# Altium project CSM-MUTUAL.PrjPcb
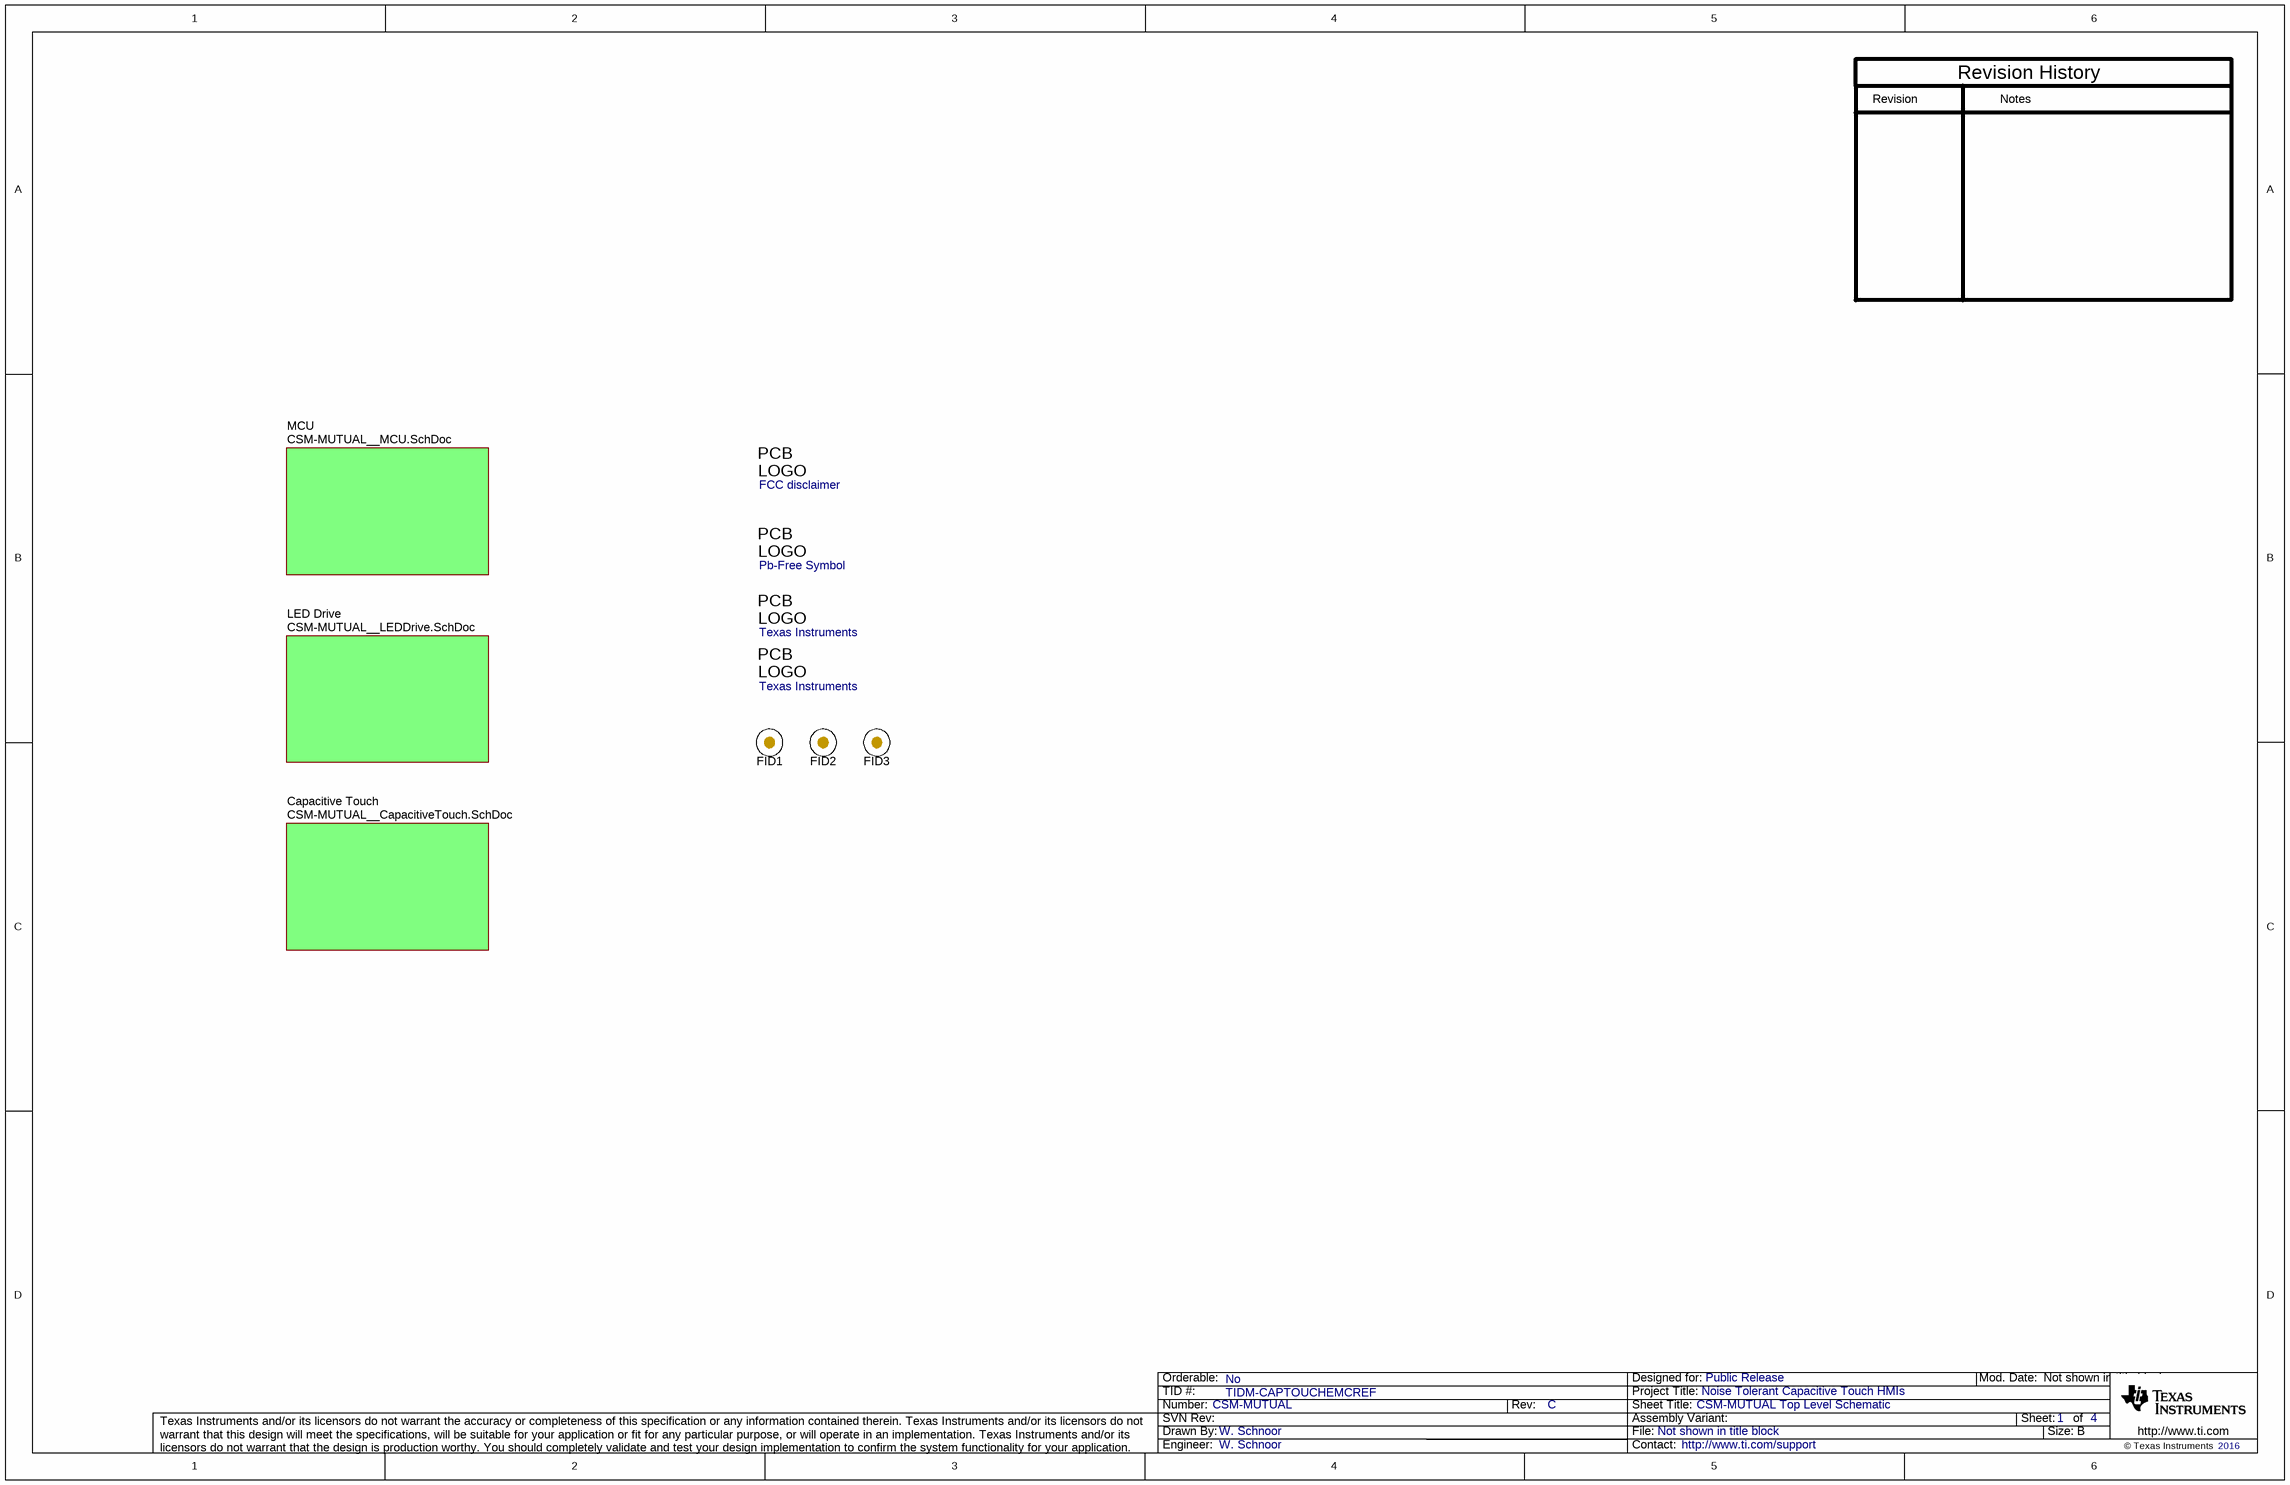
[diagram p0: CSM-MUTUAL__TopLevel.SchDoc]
TID: TIDM-CAPTOUCHEMCREF; TechSupport: http://www.ti.com/support; SCH_Rev: C; PRJ_Title: Noise Tolerant Capacitive Touch HMIs; PRJ_Number: CSM-MUTUAL; PRJ_Engineer: W. Schnoor; PRJ_Customer: Public Release; PCB_Rev: C; PCB_Layout: W. Schnoor; EVM_Orderable: No; CopyrightYear: 2016
4 sheets, 159 parts. Net scope: global (net labels, ports and power ports of the same name join across sheets).
Board file: CSM-MUTUAL.PcbDoc
Sheets:
  CSM-MUTUAL__TopLevel.SchDoc
    Capacitive Touch = CSM-MUTUAL__CapacitiveTouch.SchDoc
    LED Drive = CSM-MUTUAL__LEDDrive.SchDoc
    MCU = CSM-MUTUAL__MCU.SchDoc

## Sheet CSM-MUTUAL__TopLevel.SchDoc: CSM-MUTUAL Top Level Schematic
size 431 x 279 mm; Date: Not shown in title block; ApprovedBy: Not shown in title block; CheckedBy: Not shown in title block; Author: Not shown in title block; CompanyName: Not shown in title block; DrawnBy: W. Schnoor; Engineer: Not shown in title block; Organization: Not shown in title block; Address1: Not shown in title block; Address2: Not shown in title block; Address3: Not shown in title block; Address4: Not shown in title block; DocumentNumber: 1; Revision: Use project parameter SCH_Rev; SheetNumber: 1; SheetTotal: 4; PageSetup: Record=PageOptions¦CenterHorizontal=True¦CenterVertical=True¦PrintScale=1.00¦XCorrection=1.00¦YCorrection=1.00¦PrintKind=0¦BorderSize=5000000¦LeftOffset=0¦BottomOffset=0¦Orientation=2¦PaperLength=1000¦PaperWidth=1000¦Scale=100¦PaperSource=15¦PrintQuality=600¦MediaType=1¦DitherType=10¦PaperKind=Letter¦PrintScaleMode=1

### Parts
FCCLogo  FCC disclaimer  [FCC_disclaimer]  (no BOM)
FID1  Fiducial  [Fiducial10-30]  (value not drawn)
FID2  Fiducial  [Fiducial10-30]  (value not drawn)
FID3  Fiducial  [Fiducial10-30]  (value not drawn)
PbFreeLogo  Pb-Free Symbol  [Pb-Free_Overlay_Medium]  (no BOM)
TILogo  Texas Instruments  [TI_Stacked_Overlay_Medium]  (no BOM)
TILogoBack  Texas Instruments  [TI_Stacked_Overlay_Medium]  (no BOM)

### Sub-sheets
Capacitive Touch = CSM-MUTUAL__CapacitiveTouch.SchDoc: no entries
LED Drive = CSM-MUTUAL__LEDDrive.SchDoc: no entries
MCU = CSM-MUTUAL__MCU.SchDoc: no entries

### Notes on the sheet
- Revision
- Notes
- Revision History

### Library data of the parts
FCCLogo = FCC_disclaimer: SymbolCreator: codlsc
FID1-FID3 = Fiducial: Fiducial mark.  There is nothing to buy or mount.; SymbolCreator: codlsc
PbFreeLogo = Pb-Free: SymbolCreator: a0412235
TILogo TILogoBack = TI_Logo: Texas Instrument Corporate Signature; SymbolCreator: a0412235

## Sheet CSM-MUTUAL__CapacitiveTouch.SchDoc: CSM-MUTUAL Capacitive Touch Schematic
size 431 x 279 mm; Date: Not shown in title block; ApprovedBy: Not shown in title block; CheckedBy: Not shown in title block; Author: Not shown in title block; CompanyName: Not shown in title block; DrawnBy: W. Schnoor; Engineer: Not shown in title block; Organization: Not shown in title block; Address1: Not shown in title block; Address2: Not shown in title block; Address3: Not shown in title block; Address4: Not shown in title block; DocumentNumber: 1; Revision: Use project parameter SCH_Rev; SheetNumber: 3; SheetTotal: 4; PageSetup: Record=PageOptions¦CenterHorizontal=True¦CenterVertical=True¦PrintScale=1.00¦XCorrection=1.00¦YCorrection=1.00¦PrintKind=0¦BorderSize=5000000¦LeftOffset=0¦BottomOffset=0¦Orientation=2¦PaperLength=1000¦PaperWidth=1000¦Scale=100¦PaperSource=15¦PrintQuality=600¦MediaType=1¦DitherType=10¦PaperKind=Letter¦PrintScaleMode=1
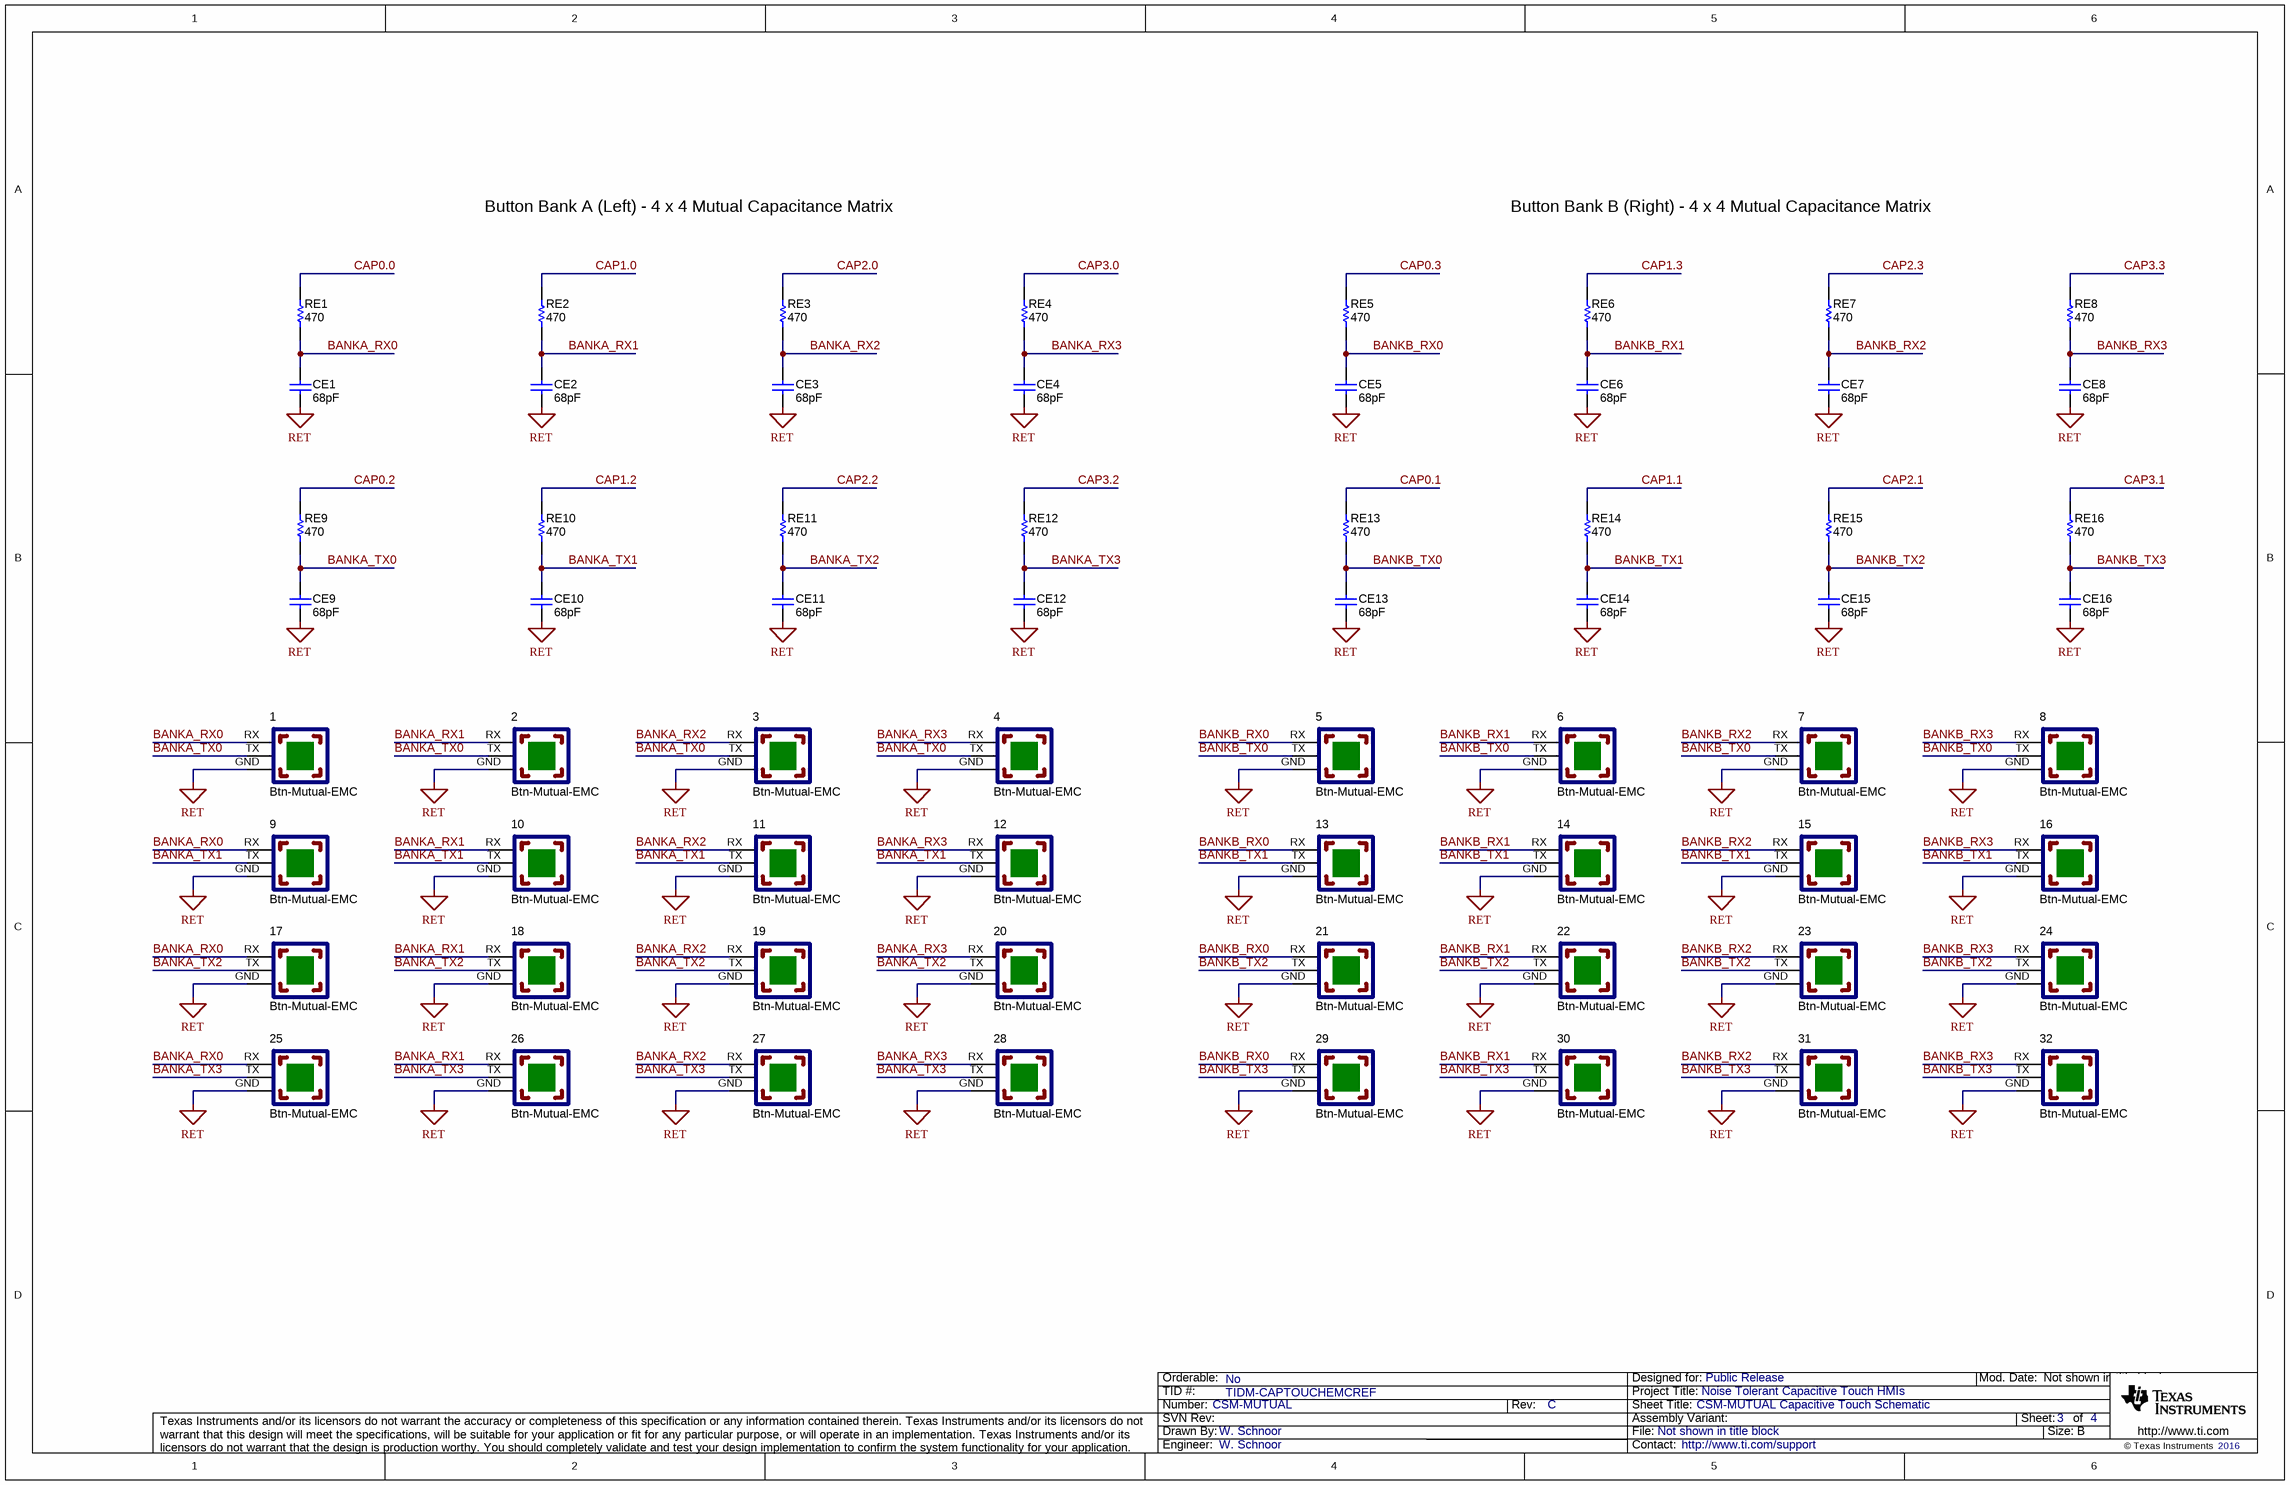
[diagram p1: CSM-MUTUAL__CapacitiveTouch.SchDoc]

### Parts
1  Btn-Mutual-EMC  [btn-mutual-emc-l-rotated]  (no BOM)
2  Btn-Mutual-EMC  [btn-mutual-emc-l-rotated]  (no BOM)
3  Btn-Mutual-EMC  [btn-mutual-emc-l-rotated]  (no BOM)
4  Btn-Mutual-EMC  [btn-mutual-emc-l-rotated]  (no BOM)
5  Btn-Mutual-EMC  [btn-mutual-emc-l-rotated]  (no BOM)
6  Btn-Mutual-EMC  [btn-mutual-emc-l-rotated]  (no BOM)
7  Btn-Mutual-EMC  [btn-mutual-emc-l-rotated]  (no BOM)
8  Btn-Mutual-EMC  [btn-mutual-emc-l-rotated]  (no BOM)
9  Btn-Mutual-EMC  [btn-mutual-emc-l-rotated]  (no BOM)
10  Btn-Mutual-EMC  [btn-mutual-emc-l-rotated]  (no BOM)
11  Btn-Mutual-EMC  [btn-mutual-emc-l-rotated]  (no BOM)
12  Btn-Mutual-EMC  [btn-mutual-emc-l-rotated]  (no BOM)
13  Btn-Mutual-EMC  [btn-mutual-emc-l-rotated]  (no BOM)
14  Btn-Mutual-EMC  [btn-mutual-emc-l-rotated]  (no BOM)
15  Btn-Mutual-EMC  [btn-mutual-emc-l-rotated]  (no BOM)
16  Btn-Mutual-EMC  [btn-mutual-emc-l-rotated]  (no BOM)
17  Btn-Mutual-EMC  [btn-mutual-emc-l-rotated]  (no BOM)
18  Btn-Mutual-EMC  [btn-mutual-emc-l-rotated]  (no BOM)
19  Btn-Mutual-EMC  [btn-mutual-emc-l-rotated]  (no BOM)
20  Btn-Mutual-EMC  [btn-mutual-emc-l-rotated]  (no BOM)
21  Btn-Mutual-EMC  [btn-mutual-emc-l-rotated]  (no BOM)
22  Btn-Mutual-EMC  [btn-mutual-emc-l-rotated]  (no BOM)
23  Btn-Mutual-EMC  [btn-mutual-emc-l-rotated]  (no BOM)
24  Btn-Mutual-EMC  [btn-mutual-emc-l-rotated]  (no BOM)
25  Btn-Mutual-EMC  [btn-mutual-emc-l-rotated]  (no BOM)
26  Btn-Mutual-EMC  [btn-mutual-emc-l-rotated]  (no BOM)
27  Btn-Mutual-EMC  [btn-mutual-emc-l-rotated]  (no BOM)
28  Btn-Mutual-EMC  [btn-mutual-emc-l-rotated]  (no BOM)
29  Btn-Mutual-EMC  [btn-mutual-emc-l-rotated]  (no BOM)
30  Btn-Mutual-EMC  [btn-mutual-emc-l-rotated]  (no BOM)
31  Btn-Mutual-EMC  [btn-mutual-emc-l-rotated]  (no BOM)
32  Btn-Mutual-EMC  [btn-mutual-emc-l-rotated]  (no BOM)
CE1  ValueDisplayed: 68pF  [0402]  (hidden comment: GRM1555C1H680JA01D)
CE2  ValueDisplayed: 68pF  [0402]  (hidden comment: GRM1555C1H680JA01D)
CE3  ValueDisplayed: 68pF  [0402]  (hidden comment: GRM1555C1H680JA01D)
CE4  ValueDisplayed: 68pF  [0402]  (hidden comment: GRM1555C1H680JA01D)
CE5  ValueDisplayed: 68pF  [0402]  (hidden comment: GRM1555C1H680JA01D)
CE6  ValueDisplayed: 68pF  [0402]  (hidden comment: GRM1555C1H680JA01D)
CE7  ValueDisplayed: 68pF  [0402]  (hidden comment: GRM1555C1H680JA01D)
CE8  ValueDisplayed: 68pF  [0402]  (hidden comment: GRM1555C1H680JA01D)
CE9  ValueDisplayed: 68pF  [0402]  (hidden comment: GRM1555C1H680JA01D)
CE10  ValueDisplayed: 68pF  [0402]  (hidden comment: GRM1555C1H680JA01D)
CE11  ValueDisplayed: 68pF  [0402]  (hidden comment: GRM1555C1H680JA01D)
CE12  ValueDisplayed: 68pF  [0402]  (hidden comment: GRM1555C1H680JA01D)
CE13  ValueDisplayed: 68pF  [0402]  (hidden comment: GRM1555C1H680JA01D)
CE14  ValueDisplayed: 68pF  [0402]  (hidden comment: GRM1555C1H680JA01D)
CE15  ValueDisplayed: 68pF  [0402]  (hidden comment: GRM1555C1H680JA01D)
CE16  ValueDisplayed: 68pF  [0402]  (hidden comment: GRM1555C1H680JA01D)
RE1  ValueDisplayed: 470  [0402]  (hidden comment: CRCW0402470RJNED)
RE2  ValueDisplayed: 470  [0402]  (hidden comment: CRCW0402470RJNED)
RE3  ValueDisplayed: 470  [0402]  (hidden comment: CRCW0402470RJNED)
RE4  ValueDisplayed: 470  [0402]  (hidden comment: CRCW0402470RJNED)
RE5  ValueDisplayed: 470  [0402]  (hidden comment: CRCW0402470RJNED)
RE6  ValueDisplayed: 470  [0402]  (hidden comment: CRCW0402470RJNED)
RE7  ValueDisplayed: 470  [0402]  (hidden comment: CRCW0402470RJNED)
RE8  ValueDisplayed: 470  [0402]  (hidden comment: CRCW0402470RJNED)
RE9  ValueDisplayed: 470  [0402]  (hidden comment: CRCW0402470RJNED)
RE10  ValueDisplayed: 470  [0402]  (hidden comment: CRCW0402470RJNED)
RE11  ValueDisplayed: 470  [0402]  (hidden comment: CRCW0402470RJNED)
RE12  ValueDisplayed: 470  [0402]  (hidden comment: CRCW0402470RJNED)
RE13  ValueDisplayed: 470  [0402]  (hidden comment: CRCW0402470RJNED)
RE14  ValueDisplayed: 470  [0402]  (hidden comment: CRCW0402470RJNED)
RE15  ValueDisplayed: 470  [0402]  (hidden comment: CRCW0402470RJNED)
RE16  ValueDisplayed: 470  [0402]  (hidden comment: CRCW0402470RJNED)

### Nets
RET: 1.GND 2.GND 3.GND 4.GND 5.GND 6.GND 7.GND 8.GND 9.GND 10.GND 11.GND 12.GND 13.GND 14.GND 15.GND 16.GND 17.GND 18.GND 19.GND 20.GND 21.GND 22.GND 23.GND 24.GND 25.GND 26.GND 27.GND 28.GND 29.GND 30.GND 31.GND 32.GND CE1.2 CE2.2 CE3.2 CE4.2 CE5.2 CE6.2 CE7.2 CE8.2 CE9.2 CE10.2 CE11.2 CE12.2 CE13.2 CE14.2 CE15.2 CE16.2
BANKA_RX0: 1.RX 9.RX 17.RX 25.RX CE1.1 RE1.1
BANKA_RX1: 2.RX 10.RX 18.RX 26.RX CE2.1 RE2.1
BANKA_RX2: 3.RX 11.RX 19.RX 27.RX CE3.1 RE3.1
BANKA_RX3: 4.RX 12.RX 20.RX 28.RX CE4.1 RE4.1
BANKA_TX0: 1.TX 2.TX 3.TX 4.TX CE9.1 RE9.1
BANKA_TX1: 9.TX 10.TX 11.TX 12.TX CE10.1 RE10.1
BANKA_TX2: 17.TX 18.TX 19.TX 20.TX CE11.1 RE11.1
BANKA_TX3: 25.TX 26.TX 27.TX 28.TX CE12.1 RE12.1
BANKB_RX0: 5.RX 13.RX 21.RX 29.RX CE5.1 RE5.1
BANKB_RX1: 6.RX 14.RX 22.RX 30.RX CE6.1 RE6.1
BANKB_RX2: 7.RX 15.RX 23.RX 31.RX CE7.1 RE7.1
BANKB_RX3: 8.RX 16.RX 24.RX 32.RX CE8.1 RE8.1
BANKB_TX0: 5.TX 6.TX 7.TX 8.TX CE13.1 RE13.1
BANKB_TX1: 13.TX 14.TX 15.TX 16.TX CE14.1 RE14.1
BANKB_TX2: 21.TX 22.TX 23.TX 24.TX CE15.1 RE15.1
BANKB_TX3: 29.TX 30.TX 31.TX 32.TX CE16.1 RE16.1
CAP0.0: RE1.2
CAP0.1: RE13.2
CAP0.2: RE9.2
CAP0.3: RE5.2
CAP1.0: RE2.2
CAP1.1: RE14.2
CAP1.2: RE10.2
CAP1.3: RE6.2
CAP2.0: RE3.2
CAP2.1: RE15.2
CAP2.2: RE11.2
CAP2.3: RE7.2
CAP3.0: RE4.2
CAP3.1: RE16.2
CAP3.2: RE12.2
CAP3.3: RE8.2

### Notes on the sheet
- Button Bank A (Left) - 4 x 4 Mutual Capacitance Matrix
- Button Bank B (Right) - 4 x 4 Mutual Capacitance Matrix

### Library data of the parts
1-32 = btn-mutual-emc: Capacitive Button, Mutual, 2-layer, EMC; Manufacturer: None; SymbolCreator: a0273983; CompType: Electrode; U/M: EA, IN, or GM
CE1-CE16 = GRM1555C1H680JA01D: CAP, CERM, 68 pF, 50 V, +/- 5%, C0G/NP0, 0402; Manufacturer: MuRata; Polarized: N; CompType: Capacitor; Value: 68pF; U/M: EA; Cap_F: 0.000000000068; Tolerance_%: 5; Value1: Unknown; VDC_V: 50; Value2: 50V; TaMin_C: -55; TaMax_C: 125; AEC Category: Q200
RE1-RE16 = CRCW0402470RJNED: RES, 470, 5%, 0.063 W, 0402; Manufacturer: Vishay-Dale; CompType: Resistor; Value: 470; Value_Code: 470R; Tolerance_%: 5; Power_W: 0.063; Value2: 0.063W; VDC_V: 50; TempCo: 200 ppm/C; EIA_Code: E24; U/M: EA; AEC Category: Q200

## Sheet CSM-MUTUAL__LEDDrive.SchDoc: CSM-MUTUAL LED Drive Schematic
size 431 x 279 mm; Date: Not shown in title block; ApprovedBy: Not shown in title block; CheckedBy: Not shown in title block; Author: Not shown in title block; CompanyName: Not shown in title block; DrawnBy: W. Schnoor; Engineer: Not shown in title block; Organization: Not shown in title block; Address1: Not shown in title block; Address2: Not shown in title block; Address3: Not shown in title block; Address4: Not shown in title block; DocumentNumber: 1; Revision: Use project parameter SCH_Rev; SheetNumber: 4; SheetTotal: 4; PageSetup: Record=PageOptions¦CenterHorizontal=True¦CenterVertical=True¦PrintScale=1.00¦XCorrection=1.00¦YCorrection=1.00¦PrintKind=0¦BorderSize=5000000¦LeftOffset=0¦BottomOffset=0¦Orientation=2¦PaperLength=1000¦PaperWidth=1000¦Scale=100¦PaperSource=15¦PrintQuality=600¦MediaType=1¦DitherType=10¦PaperKind=Letter¦PrintScaleMode=1
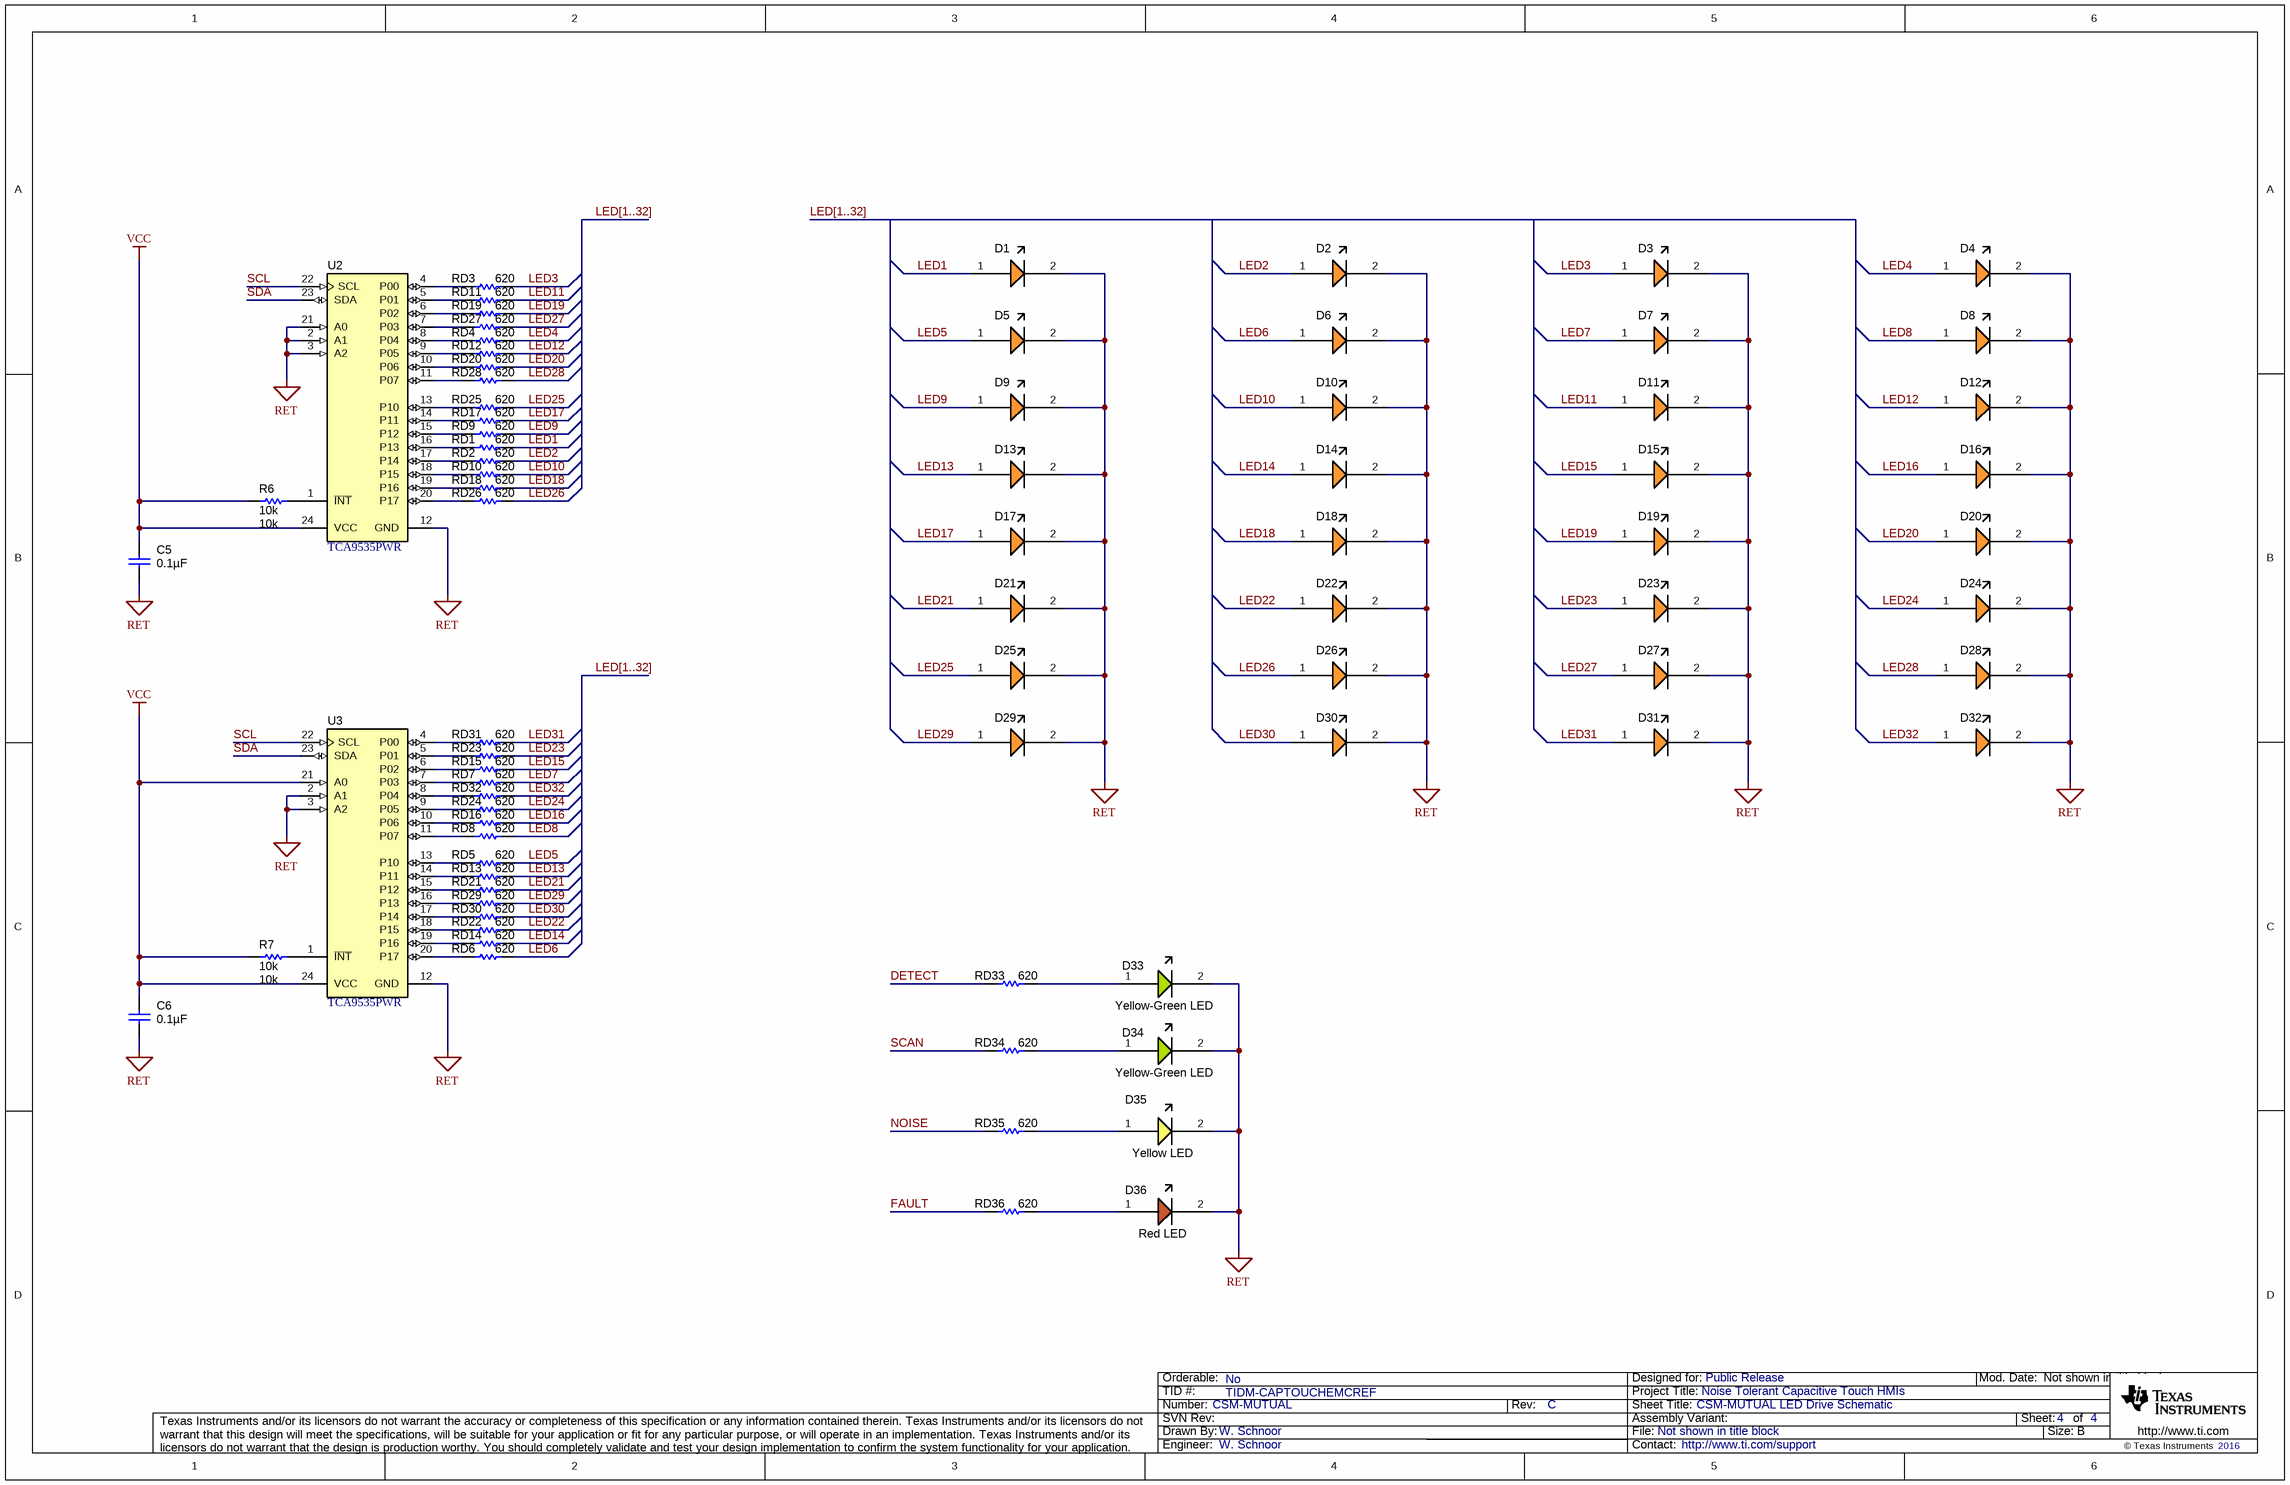
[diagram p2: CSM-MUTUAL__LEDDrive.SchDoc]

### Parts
C5  ValueDisplayed: 0.1µF  [0603]  (hidden comment: 0603YC104JAT2A)
C6  ValueDisplayed: 0.1µF  [0603]  (hidden comment: 0603YC104JAT2A)
D1  Orange LED  [1206_ReverseMount_LED]  (value not drawn)
D2  Orange LED  [1206_ReverseMount_LED]  (value not drawn)
D3  Orange LED  [1206_ReverseMount_LED]  (value not drawn)
D4  Orange LED  [1206_ReverseMount_LED]  (value not drawn)
D5  Orange LED  [1206_ReverseMount_LED]  (value not drawn)
D6  Orange LED  [1206_ReverseMount_LED]  (value not drawn)
D7  Orange LED  [1206_ReverseMount_LED]  (value not drawn)
D8  Orange LED  [1206_ReverseMount_LED]  (value not drawn)
D9  Orange LED  [1206_ReverseMount_LED]  (value not drawn)
D10  Orange LED  [1206_ReverseMount_LED]  (value not drawn)
D11  Orange LED  [1206_ReverseMount_LED]  (value not drawn)
D12  Orange LED  [1206_ReverseMount_LED]  (value not drawn)
D13  Orange LED  [1206_ReverseMount_LED]  (value not drawn)
D14  Orange LED  [1206_ReverseMount_LED]  (value not drawn)
D15  Orange LED  [1206_ReverseMount_LED]  (value not drawn)
D16  Orange LED  [1206_ReverseMount_LED]  (value not drawn)
D17  Orange LED  [1206_ReverseMount_LED]  (value not drawn)
D18  Orange LED  [1206_ReverseMount_LED]  (value not drawn)
D19  Orange LED  [1206_ReverseMount_LED]  (value not drawn)
D20  Orange LED  [1206_ReverseMount_LED]  (value not drawn)
D21  Orange LED  [1206_ReverseMount_LED]  (value not drawn)
D22  Orange LED  [1206_ReverseMount_LED]  (value not drawn)
D23  Orange LED  [1206_ReverseMount_LED]  (value not drawn)
D24  Orange LED  [1206_ReverseMount_LED]  (value not drawn)
D25  Orange LED  [1206_ReverseMount_LED]  (value not drawn)
D26  Orange LED  [1206_ReverseMount_LED]  (value not drawn)
D27  Orange LED  [1206_ReverseMount_LED]  (value not drawn)
D28  Orange LED  [1206_ReverseMount_LED]  (value not drawn)
D29  Orange LED  [1206_ReverseMount_LED]  (value not drawn)
D30  Orange LED  [1206_ReverseMount_LED]  (value not drawn)
D31  Orange LED  [1206_ReverseMount_LED]  (value not drawn)
D32  Orange LED  [1206_ReverseMount_LED]  (value not drawn)
D33  Yellow-Green LED  [1206_ReverseMount_LED]
D34  Yellow-Green LED  [1206_ReverseMount_LED]
D35  Yellow LED  [1206_ReverseMount_LED]
D36  Red LED  [1206_ReverseMount_LED]
R6  value 10k  [0603]  (hidden comment: CRCW060310K0JNEA)
R7  value 10k  [0603]  (hidden comment: CRCW060310K0JNEA)
RD1  ValueDisplayed: 620  [0402]  (hidden comment: CRCW0402620RJNED)
RD2  ValueDisplayed: 620  [0402]  (hidden comment: CRCW0402620RJNED)
RD3  ValueDisplayed: 620  [0402]  (hidden comment: CRCW0402620RJNED)
RD4  ValueDisplayed: 620  [0402]  (hidden comment: CRCW0402620RJNED)
RD5  ValueDisplayed: 620  [0402]  (hidden comment: CRCW0402620RJNED)
RD6  ValueDisplayed: 620  [0402]  (hidden comment: CRCW0402620RJNED)
RD7  ValueDisplayed: 620  [0402]  (hidden comment: CRCW0402620RJNED)
RD8  ValueDisplayed: 620  [0402]  (hidden comment: CRCW0402620RJNED)
RD9  ValueDisplayed: 620  [0402]  (hidden comment: CRCW0402620RJNED)
RD10  ValueDisplayed: 620  [0402]  (hidden comment: CRCW0402620RJNED)
RD11  ValueDisplayed: 620  [0402]  (hidden comment: CRCW0402620RJNED)
RD12  ValueDisplayed: 620  [0402]  (hidden comment: CRCW0402620RJNED)
RD13  ValueDisplayed: 620  [0402]  (hidden comment: CRCW0402620RJNED)
RD14  ValueDisplayed: 620  [0402]  (hidden comment: CRCW0402620RJNED)
RD15  ValueDisplayed: 620  [0402]  (hidden comment: CRCW0402620RJNED)
RD16  ValueDisplayed: 620  [0402]  (hidden comment: CRCW0402620RJNED)
RD17  ValueDisplayed: 620  [0402]  (hidden comment: CRCW0402620RJNED)
RD18  ValueDisplayed: 620  [0402]  (hidden comment: CRCW0402620RJNED)
RD19  ValueDisplayed: 620  [0402]  (hidden comment: CRCW0402620RJNED)
RD20  ValueDisplayed: 620  [0402]  (hidden comment: CRCW0402620RJNED)
RD21  ValueDisplayed: 620  [0402]  (hidden comment: CRCW0402620RJNED)
RD22  ValueDisplayed: 620  [0402]  (hidden comment: CRCW0402620RJNED)
RD23  ValueDisplayed: 620  [0402]  (hidden comment: CRCW0402620RJNED)
RD24  ValueDisplayed: 620  [0402]  (hidden comment: CRCW0402620RJNED)
RD25  ValueDisplayed: 620  [0402]  (hidden comment: CRCW0402620RJNED)
RD26  ValueDisplayed: 620  [0402]  (hidden comment: CRCW0402620RJNED)
RD27  ValueDisplayed: 620  [0402]  (hidden comment: CRCW0402620RJNED)
RD28  ValueDisplayed: 620  [0402]  (hidden comment: CRCW0402620RJNED)
RD29  ValueDisplayed: 620  [0402]  (hidden comment: CRCW0402620RJNED)
RD30  ValueDisplayed: 620  [0402]  (hidden comment: CRCW0402620RJNED)
RD31  ValueDisplayed: 620  [0402]  (hidden comment: CRCW0402620RJNED)
RD32  ValueDisplayed: 620  [0402]  (hidden comment: CRCW0402620RJNED)
RD33  ValueDisplayed: 620  [0402]  (hidden comment: CRCW0402620RJNED)
RD34  ValueDisplayed: 620  [0402]  (hidden comment: CRCW0402620RJNED)
RD35  ValueDisplayed: 620  [0402]  (hidden comment: CRCW0402620RJNED)
RD36  ValueDisplayed: 620  [0402]  (hidden comment: CRCW0402620RJNED)
U2  TCA9535PWR  [PW0024A_N]
U3  TCA9535PWR  [PW0024A_N]

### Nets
RET: C5.2 C6.2 D1.2(Cathode) D2.2(Cathode) D3.2(Cathode) D4.2(Cathode) D5.2(Cathode) D6.2(Cathode) D7.2(Cathode) D8.2(Cathode) D9.2(Cathode) D10.2(Cathode) D11.2(Cathode) D12.2(Cathode) D13.2(Cathode) D14.2(Cathode) D15.2(Cathode) D16.2(Cathode) D17.2(Cathode) D18.2(Cathode) D19.2(Cathode) D20.2(Cathode) D21.2(Cathode) D22.2(Cathode) D23.2(Cathode) D24.2(Cathode) D25.2(Cathode) D26.2(Cathode) D27.2(Cathode) D28.2(Cathode) D29.2(Cathode) D30.2(Cathode) D31.2(Cathode) D32.2(Cathode) D33.2(Cathode) D34.2(Cathode) D35.2(Cathode) D36.2(Cathode) U2.2(A1) U2.3(A2) U2.12(GND) U2.21(A0) U3.2(A1) U3.3(A2) U3.12(GND)
VCC: C5.1 C6.1 R6.1 R7.1 U2.24(VCC) U3.21(A0) U3.24(VCC)
DETECT: RD33.1
FAULT: RD36.1
LED1: D1.1(Anode) RD1.2
LED2: D2.1(Anode) RD2.2
LED3: D3.1(Anode) RD3.2
LED4: D4.1(Anode) RD4.2
LED5: D5.1(Anode) RD5.2
LED6: D6.1(Anode) RD6.2
LED7: D7.1(Anode) RD7.2
LED8: D8.1(Anode) RD8.2
LED9: D9.1(Anode) RD9.2
LED10: D10.1(Anode) RD10.2
LED11: D11.1(Anode) RD11.2
LED12: D12.1(Anode) RD12.2
LED13: D13.1(Anode) RD13.2
LED14: D14.1(Anode) RD14.2
LED15: D15.1(Anode) RD15.2
LED16: D16.1(Anode) RD16.2
LED17: D17.1(Anode) RD17.2
LED18: D18.1(Anode) RD18.2
LED19: D19.1(Anode) RD19.2
LED20: D20.1(Anode) RD20.2
LED21: D21.1(Anode) RD21.2
LED22: D22.1(Anode) RD22.2
LED23: D23.1(Anode) RD23.2
LED24: D24.1(Anode) RD24.2
LED25: D25.1(Anode) RD25.2
LED26: D26.1(Anode) RD26.2
LED27: D27.1(Anode) RD27.2
LED28: D28.1(Anode) RD28.2
LED29: D29.1(Anode) RD29.2
LED30: D30.1(Anode) RD30.2
LED31: D31.1(Anode) RD31.2
LED32: D32.1(Anode) RD32.2
NOISE: RD35.1
SCAN: RD34.1
SCL: U2.22(SCL) U3.22(SCL)
SDA: U2.23(SDA) U3.23(SDA)
NetD33_1: D33.1(Anode) RD33.2
NetD34_1: D34.1(Anode) RD34.2
NetD35_1: D35.1(Anode) RD35.2
NetD36_1: D36.1(Anode) RD36.2
NetR6_2: R6.2 U2.1(~{INT})
NetR7_2: R7.2 U3.1(~{INT})
NetRD1_1: RD1.1 U2.16(P13)
NetRD2_1: RD2.1 U2.17(P14)
NetRD3_1: RD3.1 U2.4(P00)
NetRD4_1: RD4.1 U2.8(P04)
NetRD5_1: RD5.1 U3.13(P10)
NetRD6_1: RD6.1 U3.20(P17)
NetRD7_1: RD7.1 U3.7(P03)
NetRD8_1: RD8.1 U3.11(P07)
NetRD9_1: RD9.1 U2.15(P12)
NetRD10_1: RD10.1 U2.18(P15)
NetRD11_1: RD11.1 U2.5(P01)
NetRD12_1: RD12.1 U2.9(P05)
NetRD13_1: RD13.1 U3.14(P11)
NetRD14_1: RD14.1 U3.19(P16)
NetRD15_1: RD15.1 U3.6(P02)
NetRD16_1: RD16.1 U3.10(P06)
NetRD17_1: RD17.1 U2.14(P11)
NetRD18_1: RD18.1 U2.19(P16)
NetRD19_1: RD19.1 U2.6(P02)
NetRD20_1: RD20.1 U2.10(P06)
NetRD21_1: RD21.1 U3.15(P12)
NetRD22_1: RD22.1 U3.18(P15)
NetRD23_1: RD23.1 U3.5(P01)
NetRD24_1: RD24.1 U3.9(P05)
NetRD25_1: RD25.1 U2.13(P10)
NetRD26_1: RD26.1 U2.20(P17)
NetRD27_1: RD27.1 U2.7(P03)
NetRD28_1: RD28.1 U2.11(P07)
NetRD29_1: RD29.1 U3.16(P13)
NetRD30_1: RD30.1 U3.17(P14)
NetRD31_1: RD31.1 U3.4(P00)
NetRD32_1: RD32.1 U3.8(P04)

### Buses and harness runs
bus LED[1..32]

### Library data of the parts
C5 C6 = 0603YC104JAT2A: CAP, CERM, 0.1 µF, 16 V, +/- 5%, X7R, 0603; Manufacturer: AVX; Polarized: N; CompType: Capacitor; Value: 0.1uF; U/M: EA; Cap_F: 0.0000001; Tolerance_%: 5; ESR_ohm: 0.039; Value1: 0.039 ohm; VDC_V: 16; Value2: 16V; TaMin_C: -55; TaMax_C: 125; AEC Category: Q200
D1-D32 = 597-6201-607F: LED, Orange, SMD, Reverse Mount, 1206; Manufacturer: Dialight; SymbolCreator: a0273983; U/M: EA, IN, or GM; Vf: 2.0-2.4V
D33 D34 = 597-6501-607F: LED, Yellow-Green, SMD, Reverse Mount, 1206; Manufacturer: Dialight; SymbolVersion: use current date i.e. 2008-05-20; SymbolCreator: a0273983; U/M: EA, IN, or GM; Vf: 1.8V-2.4V
D35 = 597-6401-607F: LED, Yellow, SMD, Reverse Mount, 1206; Manufacturer: Dialight; SymbolVersion: use current date i.e. 2008-05-20; SymbolCreator: a0273983; U/M: EA, IN, or GM; Vf: 2.0-3.4V
D36 = 597-6001-607F: LED, Red, SMD, Reverse Mount, 1206; Manufacturer: Dialight; SymbolCreator: a0273983; U/M: EA, IN, or GM; Vf: 2.0V-2.4V
R6 R7 = CRCW060310K0JNEA: RES, 10 k, 5%, 0.1 W, 0603; Manufacturer: Vishay-Dale; CompType: Resistor; Res_ohm: 10000; Value_Code: 10k0; Tolerance_%: 5; Power_W: 0.1; Value2: 0.1W; VDC_V: 75; TempCo: 200 ppm/C; EIA_Code: E24; U/M: EA; AEC Category: Q200
RD1-RD36 = CRCW0402620RJNED: RES, 620, 5%, 0.063 W, 0402; Manufacturer: Vishay-Dale; CompType: Resistor; Value: 620; Value_Code: 620R; Tolerance_%: 5; Power_W: 0.063; Value2: 0.063W; VDC_V: 50; TempCo: 200 ppm/C; EIA_Code: E24; U/M: EA; AEC Category: Q200
U2 U3 = TCA9535PWR: Remote 16-Bit I2C and SMBus, Low-Power I/O Expander with Interrupt Output and Config Register, 1.65 to 5.5 V, -40 to 85 degC, 24-pin TSSOP (PW), Green (RoHS & no Sb/Br); Manufacturer: Texas Instruments; Alternate PartNumber: Equivalent; SubFamily: I2C IO Expander; Interrupt Output: Yes; Max Frequency(kHz): 400; I2C Address: 0100 xxx; # of I/Os: 16

## Sheet CSM-MUTUAL__MCU.SchDoc: CSM-MUTUAL MCU Schematic
size 431 x 279 mm; Date: Not shown in title block; ApprovedBy: Not shown in title block; CheckedBy: Not shown in title block; Author: Not shown in title block; CompanyName: Not shown in title block; DrawnBy: W. Schnoor; Engineer: Not shown in title block; Organization: Not shown in title block; Address1: Not shown in title block; Address2: Not shown in title block; Address3: Not shown in title block; Address4: Not shown in title block; DocumentNumber: 1; Revision: Use project parameter SCH_Rev; SheetNumber: 2; SheetTotal: 4; PageSetup: Record=PageOptions¦CenterHorizontal=True¦CenterVertical=True¦PrintScale=1.00¦XCorrection=1.00¦YCorrection=1.00¦PrintKind=0¦BorderSize=5000000¦LeftOffset=0¦BottomOffset=0¦Orientation=2¦PaperLength=1000¦PaperWidth=1000¦Scale=100¦PaperSource=15¦PrintQuality=600¦MediaType=1¦DitherType=10¦PaperKind=Letter¦PrintScaleMode=1
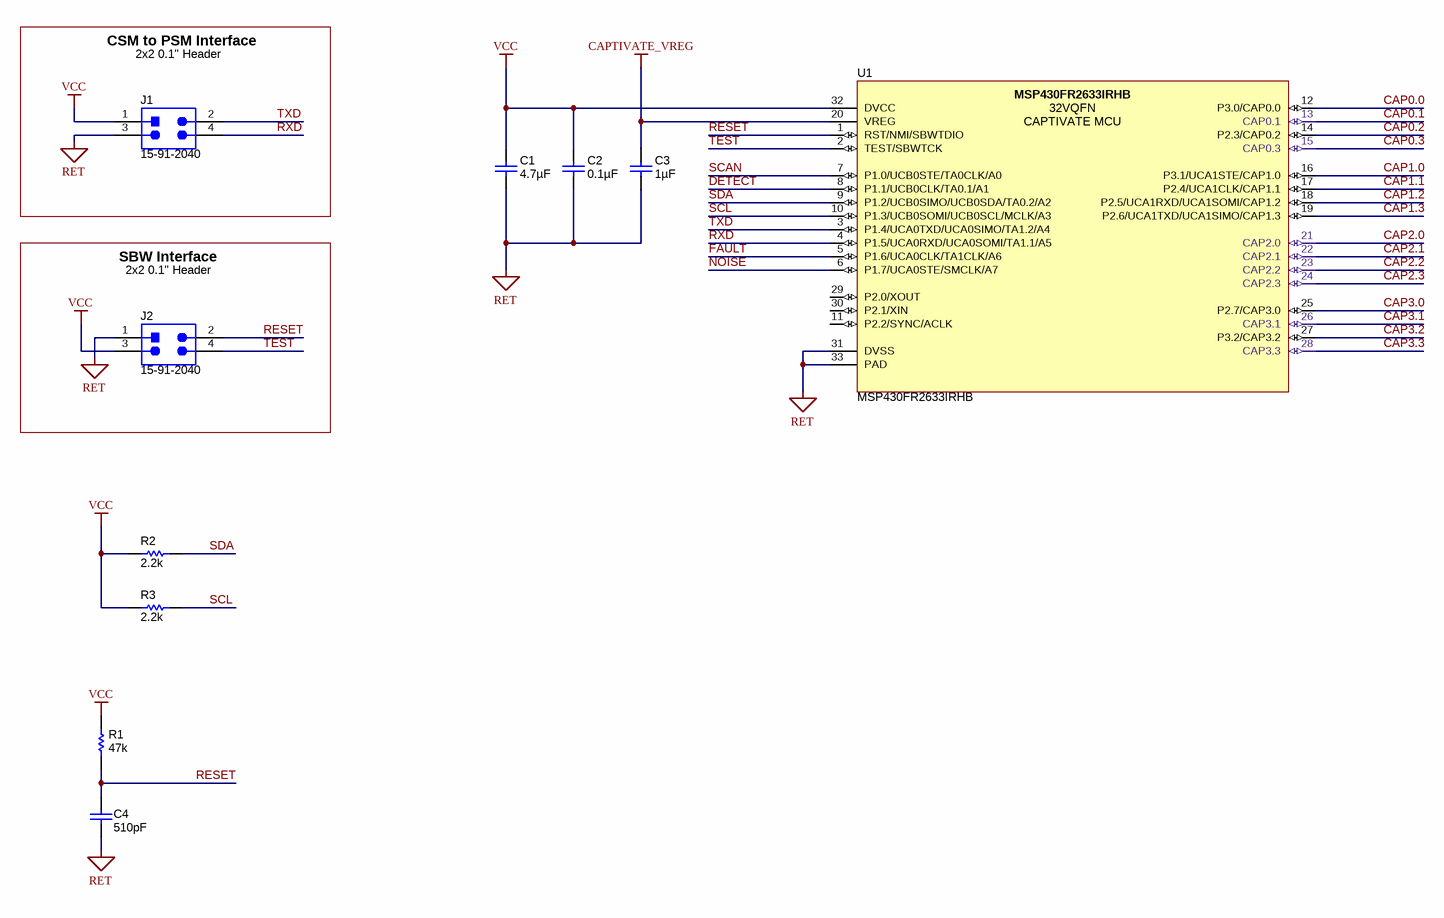
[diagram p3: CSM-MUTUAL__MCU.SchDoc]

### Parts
C1  ValueDisplayed: 4.7µF  [0402]  (hidden comment: C1005X5R0J475M050BC)
C2  ValueDisplayed: 0.1µF  [0402]  (hidden comment: C1005X5R0J104K)
C3  ValueDisplayed: 1µF  [0402]  (hidden comment: C1005X5R0J105M)
C4  ValueDisplayed: 510pF  [0402]  (hidden comment: GRM1555C1E511JA01D)
J1  15-91-2040  [Molex_15-91-2040]
J2  15-91-2040  [Molex_15-91-2040]
R1  ValueDisplayed: 47k  [0402]  (hidden comment: CRCW040247K0JNED)
R2  ValueDisplayed: 2.2k  [0402]  (hidden comment: CRCW04022K20JNED)
R3  ValueDisplayed: 2.2k  [0402]  (hidden comment: CRCW04022K20JNED)
U1  MSP430FR2633IRHB  [RHB0032E_NV]

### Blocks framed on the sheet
CSM to PSM Interface: J1
SBW Interface: J2

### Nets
CAPTIVATE_VREG: C3.1 U1.20(VREG)
RET: C1.2 C2.2 C3.2 C4.2 J1.3 J2.1 U1.31(DVSS) U1.33(PAD)
VCC: C1.1 C2.1 J1.1 J2.3 R1.2 R2.1 R3.1 U1.32(DVCC)
CAP0.0: U1.12(P3.0/CAP0.0)
CAP0.1: U1.13(CAP0.1)
CAP0.2: U1.14(P2.3/CAP0.2)
CAP0.3: U1.15(CAP0.3)
CAP1.0: U1.16(P3.1/UCA1STE/CAP1.0)
CAP1.1: U1.17(P2.4/UCA1CLK/CAP1.1)
CAP1.2: U1.18(P2.5/UCA1RXD/UCA1SOMI/CAP1.2)
CAP1.3: U1.19(P2.6/UCA1TXD/UCA1SIMO/CAP1.3)
CAP2.0: U1.21(CAP2.0)
CAP2.1: U1.22(CAP2.1)
CAP2.2: U1.23(CAP2.2)
CAP2.3: U1.24(CAP2.3)
CAP3.0: U1.25(P2.7/CAP3.0)
CAP3.1: U1.26(CAP3.1)
CAP3.2: U1.27(P3.2/CAP3.2)
CAP3.3: U1.28(CAP3.3)
DETECT: U1.8(P1.1/UCB0CLK/TA0.1/A1)
FAULT: U1.5(P1.6/UCA0CLK/TA1CLK/A6)
NOISE: U1.6(P1.7/UCA0STE/SMCLK/A7)
RESET: C4.1 J2.2 R1.1 U1.1(RST/NMI/SBWTDIO)
RXD: J1.4 U1.4(P1.5/UCA0RXD/UCA0SOMI/TA1.1/A5)
SCAN: U1.7(P1.0/UCB0STE/TA0CLK/A0)
SCL: R3.2 U1.10(P1.3/UCB0SOMI/UCB0SCL/MCLK/A3)
SDA: R2.2 U1.9(P1.2/UCB0SIMO/UCB0SDA/TA0.2/A2)
TEST: J2.4 U1.2(TEST/SBWTCK)
TXD: J1.2 U1.3(P1.4/UCA0TXD/UCA0SIMO/TA1.2/A4)

Not connected (* = marked no-connect by the designer): U1 11(P2.2/SYNC/ACLK) 29(P2.0/XOUT) 30(P2.1/XIN)

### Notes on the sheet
- 2x2 0.1" Header

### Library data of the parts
C1 = C1005X5R0J475M050BC: CAP, CERM, 4.7 µF, 6.3 V, +/- 20%, X5R, 0402; Manufacturer: TDK; Polarized: N; CompType: Capacitor; Value: 4.7uF; U/M: EA; Cap_F: 0.0000047; Tolerance_%: 20; Value1: Unknown; VDC_V: 6.3; Value2: 6.3V; TaMin_C: -55; TaMax_C: 85; AEC Category: Q200
C2 = C1005X5R0J104K: CAP, CERM, 0.1 µF, 6.3 V, +/- 10%, X5R, 0402; Manufacturer: TDK; Polarized: N; CompType: Capacitor; Value: 0.1uF; U/M: EA; Cap_F: 0.0000001; Tolerance_%: 10; ESR_ohm: 0.0186; Value1: 0.0186 ohm; VDC_V: 6.3; Value2: 6.3V; TaMin_C: -55; TaMax_C: 85; AEC Category: Q200
C3 = C1005X5R0J105M: CAP, CERM, 1 µF, 6.3 V, +/- 20%, X5R, 0402; Manufacturer: TDK; Polarized: N; CompType: Capacitor; Value: 1uF; U/M: EA; Cap_F: 0.000001; Tolerance_%: 20; ESR_ohm: 0.0079; Value1: 0.0079 ohm; VDC_V: 6.3; Value2: 6.3V; TaMin_C: -55; TaMax_C: 85; AEC Category: Q200
C4 = GRM1555C1E511JA01D: CAP, CERM, 510 pF, 25 V, +/- 5%, C0G/NP0, 0402; Manufacturer: MuRata; Polarized: N; CompType: Capacitor; Value: 510pF; U/M: EA; Cap_F: 0.00000000051; Tolerance_%: 5; Value1: Unknown; VDC_V: 25; Value2: 25V; TaMin_C: -55; TaMax_C: 125; AEC Category: Q200
J1 J2 = 15-91-2040: Header, 100mil, 2x2, Tin, SMT; Manufacturer: Molex; SymbolCreator: a0412235
R1 = CRCW040247K0JNED: RES, 47 k, 5%, 0.063 W, 0402; Manufacturer: Vishay-Dale; CompType: Resistor; Value: 47k; Res_ohm: 47000; Value_Code: 47k0; Tolerance_%: 5; Power_W: 0.063; Value2: 0.063W; VDC_V: 50; TempCo: 200 ppm/C; EIA_Code: E24; U/M: EA; AEC Category: Q200
R2 R3 = CRCW04022K20JNED: RES, 2.2 k, 5%, 0.063 W, 0402; Manufacturer: Vishay-Dale; CompType: Resistor; Value: 2.2k; Res_ohm: 2200; Value_Code: 2k20; Tolerance_%: 5; Power_W: 0.063; Value2: 0.063W; VDC_V: 50; TempCo: 200 ppm/C; EIA_Code: E24; U/M: EA; AEC Category: Q200
U1 = MSP430FR2633IRHB: MSP430 Captivate Microcontroller; Manufacturer: Texas Instruments; SymbolCreator: W. Schnoor; CompType: IC; U/M: EA, IN, or GM

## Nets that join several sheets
RET: CSM-MUTUAL__CapacitiveTouch (48 pins), CSM-MUTUAL__LEDDrive (45 pins), CSM-MUTUAL__MCU (8 pins)
VCC: CSM-MUTUAL__LEDDrive (7 pins), CSM-MUTUAL__MCU (8 pins)
CAP0.0: CSM-MUTUAL__CapacitiveTouch (RE1.2), CSM-MUTUAL__MCU (U1.12)
CAP0.1: CSM-MUTUAL__CapacitiveTouch (RE13.2), CSM-MUTUAL__MCU (U1.13)
CAP0.2: CSM-MUTUAL__CapacitiveTouch (RE9.2), CSM-MUTUAL__MCU (U1.14)
CAP0.3: CSM-MUTUAL__CapacitiveTouch (RE5.2), CSM-MUTUAL__MCU (U1.15)
CAP1.0: CSM-MUTUAL__CapacitiveTouch (RE2.2), CSM-MUTUAL__MCU (U1.16)
CAP1.1: CSM-MUTUAL__CapacitiveTouch (RE14.2), CSM-MUTUAL__MCU (U1.17)
CAP1.2: CSM-MUTUAL__CapacitiveTouch (RE10.2), CSM-MUTUAL__MCU (U1.18)
CAP1.3: CSM-MUTUAL__CapacitiveTouch (RE6.2), CSM-MUTUAL__MCU (U1.19)
CAP2.0: CSM-MUTUAL__CapacitiveTouch (RE3.2), CSM-MUTUAL__MCU (U1.21)
CAP2.1: CSM-MUTUAL__CapacitiveTouch (RE15.2), CSM-MUTUAL__MCU (U1.22)
CAP2.2: CSM-MUTUAL__CapacitiveTouch (RE11.2), CSM-MUTUAL__MCU (U1.23)
CAP2.3: CSM-MUTUAL__CapacitiveTouch (RE7.2), CSM-MUTUAL__MCU (U1.24)
CAP3.0: CSM-MUTUAL__CapacitiveTouch (RE4.2), CSM-MUTUAL__MCU (U1.25)
CAP3.1: CSM-MUTUAL__CapacitiveTouch (RE16.2), CSM-MUTUAL__MCU (U1.26)
CAP3.2: CSM-MUTUAL__CapacitiveTouch (RE12.2), CSM-MUTUAL__MCU (U1.27)
CAP3.3: CSM-MUTUAL__CapacitiveTouch (RE8.2), CSM-MUTUAL__MCU (U1.28)
DETECT: CSM-MUTUAL__LEDDrive (RD33.1), CSM-MUTUAL__MCU (U1.8)
FAULT: CSM-MUTUAL__LEDDrive (RD36.1), CSM-MUTUAL__MCU (U1.5)
NOISE: CSM-MUTUAL__LEDDrive (RD35.1), CSM-MUTUAL__MCU (U1.6)
SCAN: CSM-MUTUAL__LEDDrive (RD34.1), CSM-MUTUAL__MCU (U1.7)
SCL: CSM-MUTUAL__LEDDrive (U2.22 U3.22), CSM-MUTUAL__MCU (R3.2 U1.10)
SDA: CSM-MUTUAL__LEDDrive (U2.23 U3.23), CSM-MUTUAL__MCU (R2.2 U1.9)

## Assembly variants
001: all parts fitted
CSM-MUTUAL: No Tx Filter Capacitors: not fitted CE9 CE10 CE11 CE12 CE13 CE14 CE15 CE16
